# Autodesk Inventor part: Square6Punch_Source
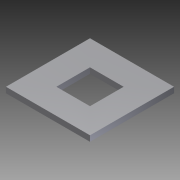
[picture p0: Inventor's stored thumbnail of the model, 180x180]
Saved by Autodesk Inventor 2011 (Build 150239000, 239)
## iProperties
Created: 2007-02
Part Number: Square6Punch_Source
Material: Default
Document SubType Name: Sheet Metal
Designer: Autodesk, Inc.
Mass: 0.189 g
Surface Area: 4.62 cm^2
Volume: 0.189 cm^3
Density: 1 g/cm^3
Sheet Metal Rule: 1 mm
Author: Autodesk, Inc.
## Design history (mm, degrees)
node "Face1"
  sketch "Sketch1"
    geometry: L1 (-7.5, 7.5)-(7.5, 7.5); L2 (7.5, 7.5)-(7.5, -7.5); L3 (7.5, -7.5)-(-7.5, -7.5); L4 (-7.5, -7.5)-(-7.5, 7.5); L5 (-7.5, 7.5)-(7.5, -7.5); 2 further points
    constraints: 10 end point, 2 parallel, 1 coincident, 1 horizontal, 1 midpoint, 1 perpendicular
    dimensions: "d0" = 15 distance of L2.end L3.end; "d1" = 15 distance of L1.end L2.end (= d0)
sketch "Sketch2"
  geometry: L1 (-3, 3)-(3, 3); L2 (3, 3)-(3, -3); L3 (3, -3)-(-3, -3); L4 (-3, -3)-(-3, 3); L5 (-3, -3)-(3, 3); 3 further points
  constraints: 10 end point, 2 coincident, 2 parallel, 1 horizontal, 1 midpoint, 1 perpendicular
  dimensions: "d3" = 6 distance of L2.end L3.end; "d4" = 6 distance of L1.end L2.end (= d3)
cut "Cut1" sketch "Sketch2" dims "d5" = 1 (= Thickness), "d6" = 0
body "Solid1"
face "Plate1" dims "Thickness" = 1
other parameters: "BendRadius" = 0.5, "BendReliefWidth" = 1 (= Thickness), "BendReliefDepth" = 0.5 (= 0.5 x Thickness), "CornerReliefSize" = 4 (= 4 x Thickness), "SeamGap" = 0.01, "MinimumRemnant" = 2 (= 2 x Thickness), "TransitionRadius" = 0.5 (= BendRadius), "JacobiRadiusSize" = 1 (= Thickness), "d2" = 0.5 (= BendRadius), "GapSize" = 1 (= Thickness)
